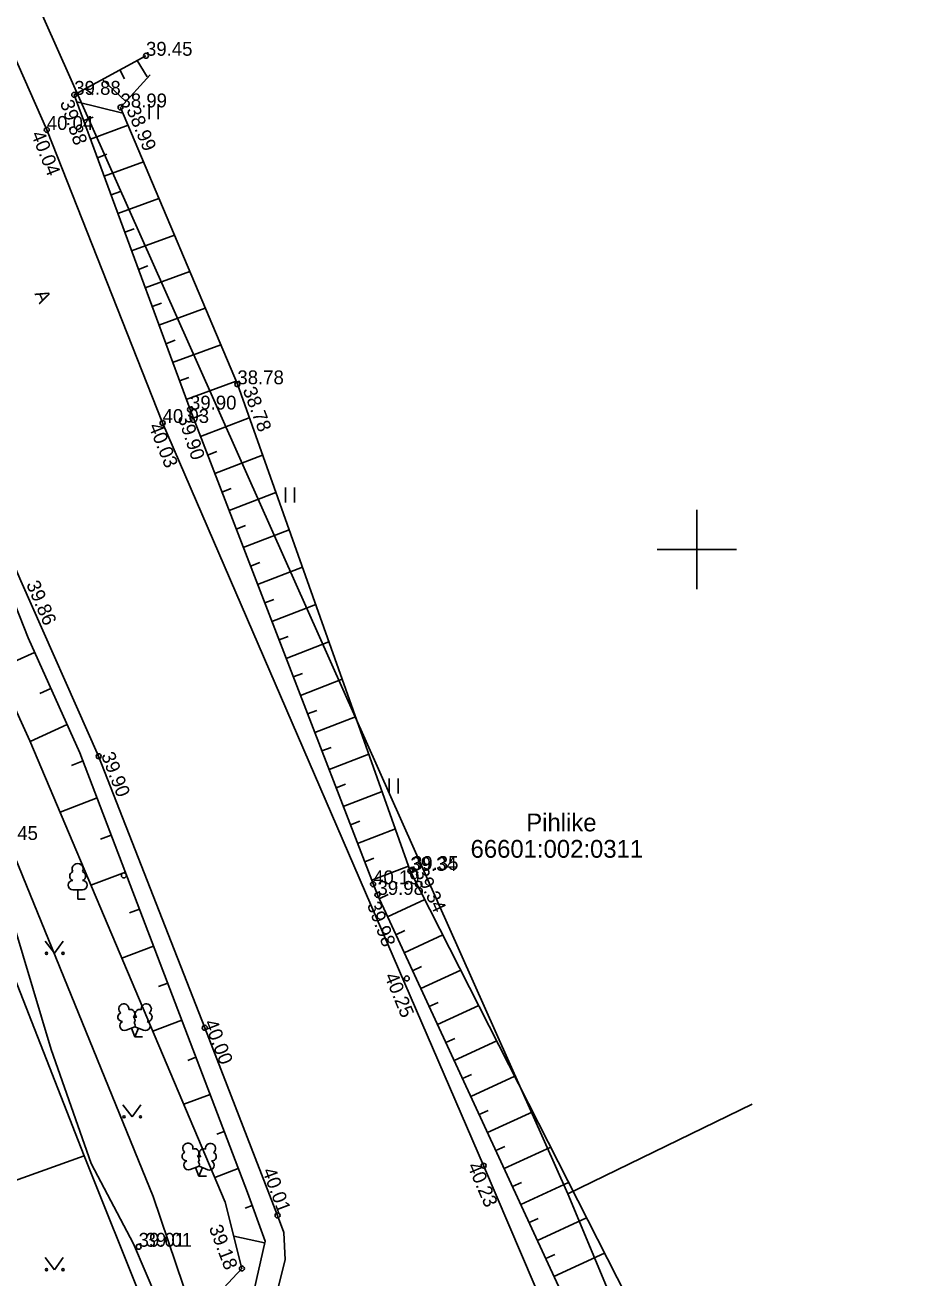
# Model space of a CAD drawing. Extents: x 627548 to 628052, y 6467984 to 6468802.
# Drawn here: x 627866.1 to 627911.6, y 6468313.2 to 6468376.5 of the extents above; entities that cross this region are included whole.
import ezdxf

# ---------------------------------------------------------------- set-up
doc = ezdxf.new("R2010")
doc.units = 0
for name, color, linetype in [('HALJASTUS', 7, 'Continuous'), ('KORGUS-EH2000', 7, 'Continuous'), ('MOOTKORG-EH2000', 7, 'Continuous'), ('MOOTMPUNKT', 7, 'Continuous'), ('PIIR', 7, 'Continuous'), ('PUU', 7, 'Continuous'), ('RELJEEF', 7, 'Continuous'), ('SITRASS', 7, 'Continuous'), ('TEE', 7, 'Continuous'), ('VORK', 7, 'Continuous')]:
    doc.layers.add(name, color=color, linetype=linetype)

msp = doc.modelspace()

# ---------------------------------------------------------------- linework, layer by layer
at = {"layer": 'HALJASTUS'}
for p, q in [((627872.396, 6468372.471), (627872.396, 6468371.71)), ((627872.851, 6468372.471), (627872.851, 6468371.71)), ((627879.264, 6468353.126), (627879.264, 6468352.365)), ((627879.719, 6468353.126), (627879.719, 6468352.365)), ((627884.496, 6468338.446), (627884.496, 6468337.685)), ((627884.951, 6468338.446), (627884.951, 6468337.685)), ((627867.159, 6468330.228), (627867.622, 6468329.621)), ((627867.622, 6468329.621), (627868.068, 6468330.228)), ((627871.068, 6468321.974), (627871.531, 6468321.368)), ((627871.531, 6468321.368), (627871.977, 6468321.974)), ((627867.159, 6468314.264), (627867.622, 6468313.657)), ((627867.622, 6468313.657), (627868.068, 6468314.264))]:
    msp.add_line(p, q, dxfattribs=at)
for centre in [(627867.221, 6468329.621), (627868.05, 6468329.621), (627871.13, 6468321.368), (627871.959, 6468321.368), (627867.221, 6468313.657), (627868.05, 6468313.657)]:
    msp.add_circle(centre, 0.055, dxfattribs=at)
at = {"layer": 'KORGUS-EH2000'}
for centre in [(627869.848, 6468339.563), (627871.121, 6468333.55), (627885.386, 6468328.351), (627875.198, 6468325.862), (627889.258, 6468318.908), (627878.868, 6468316.397), (627877.069, 6468313.719)]:
    msp.add_circle(centre, 0.125, dxfattribs=at)
at = {"layer": 'MOOTMPUNKT'}
for centre in [(627872.236, 6468374.908), (627868.619, 6468372.938), (627870.95, 6468372.302), (627867.233, 6468371.168), (627876.843, 6468358.333), (627874.455, 6468357.057), (627873.073, 6468356.381), (627885.562, 6468333.781), (627885.646, 6468333.827), (627883.686, 6468333.106), (627883.906, 6468332.57), (627871.865, 6468314.815)]:
    msp.add_circle(centre, 0.125, dxfattribs=at)
at = {"layer": 'PIIR'}
for p, q in [((627893.5, 6468317.49), (627836.88, 6468444.6)), ((627860.61, 6468341.12), (627869.12, 6468319.4)), ((627893.5, 6468317.49), (627902.801, 6468322.015)), ((627857.089, 6468315.074), (627869.12, 6468319.4)), ((627869.12, 6468319.4), (627897.87, 6468247.69)), ((627912.59, 6468271.79), (627893.5, 6468317.49))]:
    msp.add_line(p, q, dxfattribs=at)
at = {"layer": 'PUU'}
for p, q in [((627869.031, 6468332.824), (627868.551, 6468332.824)), ((627868.791, 6468332.349), (627868.791, 6468332.824)), ((627869.171, 6468332.349), (627868.791, 6468332.349)), ((627871.232, 6468325.741), (627871.677, 6468325.916)), ((627871.672, 6468325.406), (627871.497, 6468325.846)), ((627871.672, 6468325.406), (627871.852, 6468325.846)), ((627871.677, 6468325.916), (627872.117, 6468325.736)), ((627872.052, 6468325.406), (627871.672, 6468325.406)), ((627874.467, 6468318.708), (627874.912, 6468318.883)), ((627874.907, 6468318.373), (627874.732, 6468318.813)), ((627874.907, 6468318.373), (627875.087, 6468318.813)), ((627874.912, 6468318.883), (627875.352, 6468318.703)), ((627875.287, 6468318.373), (627874.907, 6468318.373))]:
    msp.add_line(p, q, dxfattribs=at)
for points in [[(627871.677, 6468326.411), (627871.657, 6468326.336), (627871.657, 6468326.316), (627871.667, 6468326.286), (627871.687, 6468326.251), (627871.692, 6468326.231), (627871.677, 6468326.196), (627871.652, 6468326.146), (627871.647, 6468326.121), (627871.652, 6468326.106), (627871.662, 6468326.076), (627871.697, 6468326.016), (627871.702, 6468325.996), (627871.697, 6468325.976), (627871.682, 6468325.941), (627871.677, 6468325.916)], [(627874.912, 6468319.378), (627874.892, 6468319.303), (627874.892, 6468319.283), (627874.902, 6468319.253), (627874.922, 6468319.218), (627874.927, 6468319.198), (627874.912, 6468319.163), (627874.887, 6468319.113), (627874.882, 6468319.088), (627874.887, 6468319.073), (627874.897, 6468319.043), (627874.932, 6468318.983), (627874.937, 6468318.963), (627874.932, 6468318.943), (627874.917, 6468318.908), (627874.912, 6468318.883)]]:
    msp.add_lwpolyline(points, dxfattribs=at)
for centre, radius, start, end in [((627868.791, 6468333.869), 0.277, 332.5799, 207.4201), ((627868.554, 6468333.061), 0.238, 90.0016, 269.3953), ((627868.621, 6468333.521), 0.233, 109.02174, 253.14154), ((627868.961, 6468333.521), 0.233, 286.85082, 70.98591), ((627869.029, 6468333.061), 0.238, 270.6047, 89.9984), ((627871.115, 6468326.82), 0.256, 111.50269, 232.51731), ((627871.115, 6468326.82), 0.256, 350.48556, 111.50017), ((627872.251, 6468326.811), 0.256, 67.6168, 188.63142), ((627872.251, 6468326.811), 0.256, 306.59966, 67.61428), ((627871.041, 6468326.409), 0.224, 111.43041, 274.49868), ((627871.45, 6468326.569), 0.224, 308.50412, 111.57247), ((627871.676, 6468326.173), 0.237, 66.76552, 111.50149), ((627871.913, 6468326.565), 0.225, 67.7016, 230.51262), ((627872.319, 6468326.399), 0.224, 264.6183, 67.68657), ((627871.146, 6468325.964), 0.237, 111.50143, 291.50036), ((627872.207, 6468325.956), 0.237, 247.61661, 67.61554), ((627874.35, 6468319.787), 0.256, 111.50269, 232.51731), ((627874.35, 6468319.787), 0.256, 350.48556, 111.50017), ((627875.486, 6468319.778), 0.256, 67.6168, 188.63142), ((627875.486, 6468319.778), 0.256, 306.59966, 67.61428), ((627874.276, 6468319.376), 0.224, 111.43041, 274.49868), ((627874.684, 6468319.537), 0.224, 308.50412, 111.57247), ((627874.911, 6468319.14), 0.237, 66.76552, 111.50149), ((627875.147, 6468319.532), 0.225, 67.7016, 230.51262), ((627875.553, 6468319.366), 0.224, 264.6183, 67.68657), ((627874.38, 6468318.931), 0.237, 111.50143, 291.50036), ((627875.442, 6468318.923), 0.237, 247.61661, 67.61554)]:
    msp.add_arc(centre, radius, start, end, dxfattribs=at)
at = {"layer": 'RELJEEF'}
for p, q in [((627871.797, 6468374.669), (627872.294, 6468373.841)), ((627870.041, 6468373.712), (627871.218, 6468372.596)), ((627870.919, 6468374.191), (627871.158, 6468373.751)), ((627869.162, 6468373.234), (627869.567, 6468372.96)), ((627868.751, 6468372.58), (627871.071, 6468372.015)), ((627869.095, 6468371.641), (627869.565, 6468371.814)), ((627869.44, 6468370.703), (627871.331, 6468371.398)), ((627869.785, 6468369.764), (627870.255, 6468369.937)), ((627870.13, 6468368.826), (627872.11, 6468369.553)), ((627870.475, 6468367.887), (627870.944, 6468368.059)), ((627870.82, 6468366.948), (627872.888, 6468367.708)), ((627871.165, 6468366.01), (627871.634, 6468366.182)), ((627871.51, 6468365.071), (627873.666, 6468365.863)), ((627871.855, 6468364.132), (627872.324, 6468364.305)), ((627872.2, 6468363.194), (627874.444, 6468364.019)), ((627872.545, 6468362.255), (627873.014, 6468362.428)), ((627872.89, 6468361.317), (627875.223, 6468362.174)), ((627873.235, 6468360.378), (627873.704, 6468360.55)), ((627873.58, 6468359.439), (627876.001, 6468360.329)), ((627873.924, 6468358.501), (627874.394, 6468358.673)), ((627874.269, 6468357.562), (627876.779, 6468358.484)), ((627874.621, 6468356.626), (627875.088, 6468356.806)), ((627874.981, 6468355.693), (627877.443, 6468356.643)), ((627875.341, 6468354.76), (627875.808, 6468354.94)), ((627875.702, 6468353.827), (627878.113, 6468354.758)), ((627876.062, 6468352.894), (627876.528, 6468353.074)), ((627876.422, 6468351.961), (627878.782, 6468352.872)), ((627876.782, 6468351.028), (627877.248, 6468351.209)), ((627877.142, 6468350.096), (627879.452, 6468350.987)), ((627877.502, 6468349.163), (627877.968, 6468349.343)), ((627877.862, 6468348.23), (627880.121, 6468349.102)), ((627878.222, 6468347.297), (627878.689, 6468347.477)), ((627878.582, 6468346.364), (627880.791, 6468347.216)), ((627878.942, 6468345.431), (627879.409, 6468345.611)), ((627879.302, 6468344.498), (627881.46, 6468345.331)), ((627866.62, 6468344.807), (627864.727, 6468343.953)), ((627879.662, 6468343.565), (627880.129, 6468343.745)), ((627880.022, 6468342.632), (627882.13, 6468343.446)), ((627867.442, 6468342.983), (627866.877, 6468342.729)), ((627880.382, 6468341.699), (627880.849, 6468341.879)), ((627880.743, 6468340.766), (627882.799, 6468341.56)), ((627868.264, 6468341.16), (627866.389, 6468340.315)), ((627881.103, 6468339.833), (627881.569, 6468340.013)), ((627881.463, 6468338.9), (627883.469, 6468339.675)), ((627869.062, 6468339.327), (627868.479, 6468339.105)), ((627881.823, 6468337.968), (627882.289, 6468338.148)), ((627882.183, 6468337.035), (627884.139, 6468337.789)), ((627869.774, 6468337.458), (627867.901, 6468336.745)), ((627882.543, 6468336.102), (627883.009, 6468336.282)), ((627882.903, 6468335.169), (627884.808, 6468335.904)), ((627870.485, 6468335.589), (627869.944, 6468335.382)), ((627883.263, 6468334.236), (627883.73, 6468334.416)), ((627883.623, 6468333.303), (627885.478, 6468334.019)), ((627871.197, 6468333.719), (627869.462, 6468333.059)), ((627883.996, 6468332.375), (627884.45, 6468332.585)), ((627884.415, 6468331.468), (627886.296, 6468332.337)), ((627871.909, 6468331.85), (627871.409, 6468331.66)), ((627884.835, 6468330.56), (627885.289, 6468330.77)), ((627872.62, 6468329.981), (627871.023, 6468329.373)), ((627885.255, 6468329.652), (627887.202, 6468330.552)), ((627885.674, 6468328.744), (627886.128, 6468328.954)), ((627886.094, 6468327.837), (627888.108, 6468328.768)), ((627873.332, 6468328.112), (627872.873, 6468327.938)), ((627886.513, 6468326.929), (627886.967, 6468327.139)), ((627886.933, 6468326.021), (627889.014, 6468326.983)), ((627874.044, 6468326.243), (627872.584, 6468325.687)), ((627887.352, 6468325.114), (627887.806, 6468325.323)), ((627887.772, 6468324.206), (627889.921, 6468325.199)), ((627874.756, 6468324.374), (627874.338, 6468324.215)), ((627888.191, 6468323.298), (627888.645, 6468323.508)), ((627888.611, 6468322.39), (627890.827, 6468323.415)), ((627875.467, 6468322.505), (627874.145, 6468322.001)), ((627889.03, 6468321.483), (627889.484, 6468321.692)), ((627889.45, 6468320.575), (627891.733, 6468321.63)), ((627876.179, 6468320.636), (627875.803, 6468320.493)), ((627889.87, 6468319.667), (627890.323, 6468319.877)), ((627890.289, 6468318.759), (627892.64, 6468319.846)), ((627876.891, 6468318.767), (627875.706, 6468318.316)), ((627890.709, 6468317.852), (627891.162, 6468318.061)), ((627891.128, 6468316.944), (627893.546, 6468318.061)), ((627877.59, 6468316.893), (627877.228, 6468316.763)), ((627891.548, 6468316.036), (627892.002, 6468316.246)), ((627891.967, 6468315.128), (627894.452, 6468316.277)), ((627878.219, 6468315.008), (627876.661, 6468315.355)), ((627892.387, 6468314.221), (627892.841, 6468314.43)), ((627892.806, 6468313.313), (627895.359, 6468314.493))]:
    msp.add_line(p, q, dxfattribs=at)
for points in [[(627798.462, 6468458.953), (627803.154, 6468462.558), (627806.385, 6468462.787), (627809.612, 6468460.426), (627831.39, 6468420.981), (627849.758, 6468382.754), (627863.845, 6468351.725), (627866.293, 6468345.533)], [(627872.236, 6468374.908), (627868.619, 6468372.938), (627874.455, 6468357.057), (627883.906, 6468332.57), (627893.555, 6468311.693), (627896.884, 6468302.582), (627898.609, 6468301.907), (627901.118, 6468302.536)], [(627872.45, 6468373.949), (627870.95, 6468372.302), (627876.843, 6468358.333), (627885.562, 6468333.781), (627896.498, 6468312.249), (627899.309, 6468303.257), (627900.953, 6468303.542)], [(627873.347, 6468309.45), (627873.83, 6468310.241), (627877.069, 6468313.719), (627876.234, 6468317.068), (627866.378, 6468340.34), (627864.296, 6468344.897), (627863.023, 6468347.157)], [(627873.346, 6468309.415), (627874.307, 6468309.823), (627877.573, 6468312.111), (627878.237, 6468315.09), (627877.354, 6468317.55), (627868.906, 6468339.736), (627866.293, 6468345.533)]]:
    msp.add_lwpolyline(points, dxfattribs=at)
at = {"layer": 'SITRASS'}
for points in [[(627895.041, 6468257.946), (627892.765, 6468263.751), (627885.861, 6468280.997), (627884.574, 6468284.991), (627881.355, 6468292.946), (627877.718, 6468303.187), (627876.72, 6468307.148), (627874.885, 6468310.594), (627872.6, 6468317.358), (627865.068, 6468335.844), (627862.702, 6468343.386), (627859.888, 6468348.841), (627858.632, 6468350.621)], [(627893.107, 6468260.449), (627888.841, 6468271.867), (627885.53, 6468279.764), (627882.135, 6468288.441), (627879.374, 6468296.292), (627875.722, 6468305.138), (627874.264, 6468308.557), (627873.961, 6468309.445), (627871.602, 6468314.968), (627869.468, 6468319.018), (627867.454, 6468324.77), (627864.183, 6468335.69), (627861.634, 6468344.011), (627861.623, 6468344.046)]]:
    msp.add_lwpolyline(points, dxfattribs=at)
at = {"layer": 'TEE'}
for points in [[(627773.875, 6468550.47), (627771.331, 6468547.778), (627770.184, 6468544.969), (627779.724, 6468530.382), (627790.194, 6468514.89), (627795.603, 6468506.268), (627810.358, 6468482.16), (627820.252, 6468465.61), (627824.787, 6468457.176), (627842.022, 6468424.68), (627853.219, 6468402.014), (627861.194, 6468384.862), (627867.233, 6468371.168), (627873.073, 6468356.381), (627889.258, 6468318.908), (627892.446, 6468311.434), (627896.87, 6468301.517), (627899.405, 6468301.54), (627901.626, 6468302.361)], [(627850.995, 6468383.192), (627865.917, 6468348.418), (627869.848, 6468339.563), (627875.198, 6468325.862), (627878.868, 6468316.397), (627879.191, 6468315.536), (627879.247, 6468314.16), (627878.907, 6468312.752), (627878.096, 6468311.241), (627877.224, 6468310.534), (627875.866, 6468309.978), (627867.479, 6468306.988), (627868.314, 6468303.013), (627877.023, 6468305.93), (627880.299, 6468306.759), (627882.65, 6468305.874), (627884.478, 6468303.721), (627886.739, 6468296.981), (627888.125, 6468293.223), (627886.174, 6468287.898), (627882.32, 6468286.813)]]:
    msp.add_lwpolyline(points, dxfattribs=at)
at = {"layer": 'VORK'}
for p, q in [((627900, 6468352), (627900, 6468348)), ((627898, 6468350), (627902, 6468350))]:
    msp.add_line(p, q, dxfattribs=at)

# ---------------------------------------------------------------- texts
at = {"layer": 'KORGUS-EH2000'}
for s, rotation, p in [('39.88', 288.524, (627867.891, 6468372.556)), ('38.99', 292.93617, (627871.233, 6468372.185)), ('40.04', 291.65975, (627866.432, 6468370.956)), ('38.78', 290.86808, (627877.102, 6468358.054)), ('39.90', 288.41739, (627873.825, 6468356.672)), ('40.03', 291.93734, (627872.354, 6468356.219)), (' 39.86', 293.46996, (627866.077, 6468348.487)), (' 39.90', 291.32977, (627869.866, 6468339.862)), ('39.34', 295.51928, (627885.764, 6468333.727)), ('39.98', 290.44161, (627883.371, 6468332.079)), (' 40.25', 292.29555, (627884.149, 6468328.715)), (' 40.00', 291.19352, (627875.053, 6468326.368)), (' 40.01', 290.56334, (627877.998, 6468318.896)), (' 40.23', 293.34756, (627888.323, 6468319.132)), (' 39.18', 290.91725, (627875.301, 6468316.015))]:
    msp.add_text(s, height=0.7, rotation=rotation, dxfattribs=at).set_placement(p)
for s, p in [(' 39.45', (627864.183, 6468335.34)), ('39.01', (627872.215, 6468314.815))]:
    msp.add_text(s, height=0.7, dxfattribs=at).set_placement(p)
at = {"layer": 'MOOTKORG-EH2000'}
for s, p in [('39.45', (627872.236, 6468374.908)), ('39.88', (627868.619, 6468372.938)), ('38.99', (627870.95, 6468372.302)), ('40.04', (627867.233, 6468371.168)), ('38.78', (627876.843, 6468358.333)), ('39.90', (627874.455, 6468357.057)), ('40.03', (627873.073, 6468356.381)), ('39.34', (627885.562, 6468333.781)), ('39.35', (627885.646, 6468333.827)), ('40.19', (627883.686, 6468333.106)), ('39.98', (627883.906, 6468332.57)), ('39.01', (627871.865, 6468314.815))]:
    msp.add_text(s, height=0.7, dxfattribs=at).set_placement(p)
at = {"layer": 'PIIR'}
for s, p in [('Pihlike', (627891.407, 6468335.773)), ('66601:002:0311', (627888.6, 6468334.442))]:
    msp.add_text(s, height=0.9, dxfattribs=at).set_placement(p)
at = {"layer": 'TEE'}
msp.add_text('A', height=0.7, rotation=295.08233, dxfattribs=at).set_placement((627866.601, 6468362.908))

doc.saveas('drawing.dxf')
